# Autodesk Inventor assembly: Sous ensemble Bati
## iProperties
Created: 2004-11
Part Number: Sous ensemble Bati
Document SubType Name: Assembly
Designer: Bruno
Manufacturer: Standard
Standards Organization: Custom
Norme de conversion: STEP AP203
Nom du fichier: Take Out.stp
Préprocesseur: Mechanical Desktop 2005
Postprocesseur: Build: 096e, Release: 9 RTM - Date: Thu 06/17/2004
Unités envoyées: MILLIMETERS
Incertitude: 1.0000000000000002e-06
Author: Bruno
